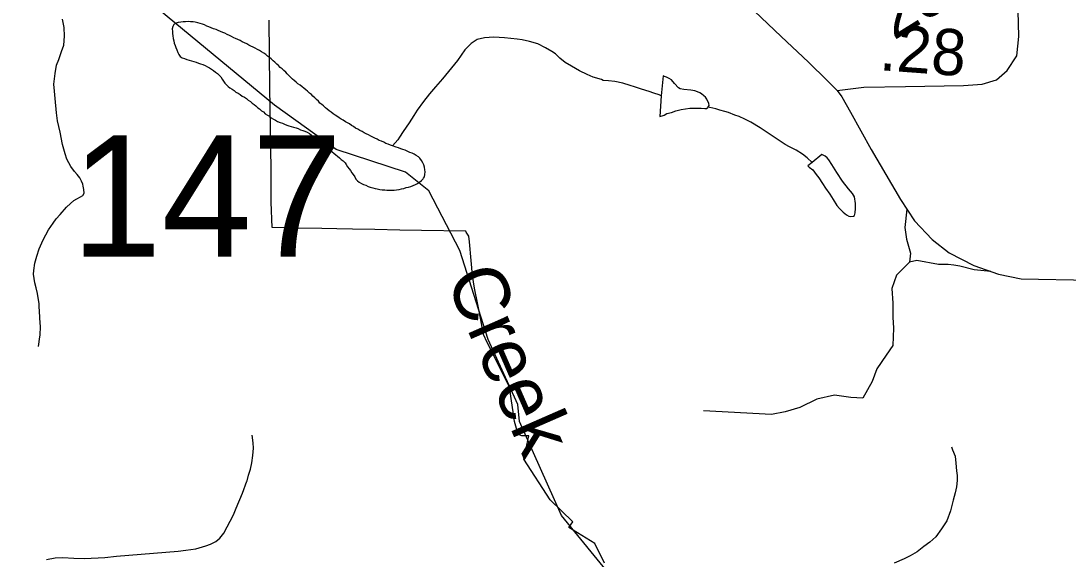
# Model space of a CAD drawing. Extents: x 2001466 to 31450019, y -30647475 to 847247.
# Drawn here: x 2153501 to 2159166, y 761240 to 764149 of the extents above; entities that cross this region are included whole.
import ezdxf

# ---------------------------------------------------------------- set-up
doc = ezdxf.new("R2010")
doc.units = 0
for name, color, linetype in [('Exist Boundary Political City Limit New', 7, 'Continuous'), ('Exist Hydrographic Creek Single Shore', 7, 'Continuous'), ('Exist Hydrographic Creek Single Shore Label', 7, 'Continuous'), ('Exist Hydrographic Misc Water Feature', 7, 'Continuous'), ('Exist Road Non-System Type 51', 7, 'Continuous'), ('Exist Road Secondary Mileage Hundredths English Label', 7, 'Continuous'), ('Exist Road Secondary Structure Standard Bridge Number Label', 7, 'Continuous'), ('Exist Road Secondary Type 51 Attributed', 7, 'Continuous'), ('Exist Road Secondary Type 51 Number Label', 7, 'Continuous'), ('Map Preparation Boundary City Limit Buffer Line', 7, 'Continuous')]:
    doc.layers.add(name, color=color, linetype=linetype)

msp = doc.modelspace()

# ---------------------------------------------------------------- linework, layer by layer
at = {"layer": 'Exist Boundary Political City Limit New'}
msp.add_lwpolyline([(2156657.8, 761217.6), (2156606, 761323.4), (2156464.8, 761410.4), (2156487, 761441.2), (2156363.2, 761559.5), (2156220.8, 761779.9), (2156249.2, 761906.5), (2156210, 761905.6), (2156195.5, 761910.8), (2156186.2, 761932.5), (2156172, 761983.3), (2156165, 762022.5), (2156152.5, 762108.3), (2156144, 762171.1), (2156023.2, 762411.2), (2156003.8, 762453.4), (2155988.5, 762533), (2155973, 762616.8), (2155955, 762703.8), (2155944, 762772.4), (2155936.2, 762853.9), (2155926.8, 762954.9), (2155923.5, 762985.4), (2155909.8, 763007.9), (2155907, 763013.1), (2155668.2, 763015.9), (2155551.2, 763017.9), (2155415.5, 763020.9), (2155295.5, 763023.9), (2155209.2, 763025.1), (2155129, 763026.2), (2155000, 763028.9), (2154859.2, 763031.7), (2154855.2, 763168.5), (2154854.5, 763348.4), (2154850.8, 763568.4), (2154847.5, 763788.2), (2154843, 764152.2)], dxfattribs=at)
at = {"layer": 'Exist Hydrographic Creek Single Shore'}
msp.add_lwpolyline([(2156794.2, 761022.6), (2156425.3, 761476.3), (2156197.3, 761982.9), (2156189.3, 762075), (2156028.3, 762426), (2155876.2, 762908.1), (2155707.2, 763229.7), (2155582.3, 763330.7), (2155206.3, 763453.2), (2154872.2, 763693.1), (2154043.2, 764379.3), (2153717.2, 764612.4), (2153524.2, 764783.6), (2153339.3, 765049.9), (2153113.3, 765274.3), (2153096.3, 765333.7)], dxfattribs=at)
at = {"layer": 'Exist Hydrographic Misc Water Feature'}
for points in [[(2153596.4, 762388.9), (2153597.8, 762400.9), (2153602.2, 762429), (2153605.6, 762452.9), (2153607.5, 762494.7), (2153603.2, 762542.9), (2153600.9, 762583), (2153599.1, 762599.1), (2153598.9, 762618.9), (2153590.5, 762675), (2153582.5, 762706.6), (2153576.3, 762732.7), (2153569.8, 762780.8), (2153570.2, 762800.6), (2153575.7, 762838.7), (2153587.4, 762876.6), (2153599.3, 762916.7), (2153620.8, 762964.9), (2153650.8, 763018.8), (2153674.5, 763055), (2153692.2, 763079.5), (2153712.3, 763103.2), (2153747.9, 763141.6), (2153769.7, 763161.9), (2153787.7, 763177.8), (2153803.7, 763188), (2153823.2, 763198), (2153835.7, 763205.9), (2153843.7, 763218), (2153841.5, 763237.8), (2153837.1, 763255.9), (2153835.5, 763265.9), (2153828.7, 763281.9), (2153825, 763289.8), (2153819.1, 763300), (2153805, 763318), (2153791, 763335.5), (2153770.7, 763361.7), (2153748.4, 763401.6), (2153740.4, 763429.6), (2153726, 763481.2), (2153713.5, 763547.2), (2153699.1, 763609), (2153693, 763653), (2153686.8, 763728.9), (2153682.5, 763768.9), (2153678.2, 763806.9), (2153685.8, 763865), (2153693.4, 763908.9), (2153705.7, 763941.1), (2153721.3, 763983.4), (2153732.8, 764017.3), (2153736.9, 764067.4), (2153734.4, 764113.2), (2153726.2, 764159.1)], [(2154417.9, 764144.9), (2154406, 764145.1), (2154391.8, 764144.8), (2154377.9, 764144.9), (2154366, 764142.6), (2154352, 764140.6), (2154340.3, 764136.7), (2154328.2, 764130.5), (2154322.1, 764118.4), (2154320, 764106.5), (2154320.2, 764092.3), (2154320.5, 764080.6), (2154322.7, 764068.5), (2154324.6, 764054.4), (2154328.7, 764040.8), (2154330.5, 764028.7), (2154334.8, 764016.7), (2154338.9, 764004.7), (2154344.9, 763992.8), (2154349, 763978.8), (2154355.1, 763966.6), (2154363.1, 763956.9), (2154373.4, 763948.8), (2154385.5, 763945), (2154397.6, 763941.1), (2154411.3, 763937), (2154423.4, 763933.1), (2154435.5, 763929.3), (2154449.2, 763925.2), (2154461.3, 763921.3), (2154473, 763917.5), (2154485.1, 763913.6), (2154497.4, 763907.7), (2154509.5, 763901.4), (2154521.2, 763895.6), (2154531.5, 763887.6), (2154543.6, 763881.7), (2154553.4, 763872.1), (2154563.6, 763864.1), (2154573.7, 763856), (2154581.9, 763845.9), (2154589.7, 763834.1), (2154596, 763824.2), (2154603.8, 763812.1), (2154611.8, 763804.4), (2154622.1, 763794.4), (2154631.9, 763786.4), (2154644, 763780.5), (2154654.1, 763772.5), (2154664.3, 763764.5), (2154676, 763758.6), (2154686.3, 763750.6), (2154698.2, 763742.7), (2154710.3, 763736.8), (2154720.5, 763728.8), (2154730.1, 763720.8), (2154742.5, 763712.9), (2154752.5, 763704.8), (2154762.8, 763697.2), (2154772.4, 763689.3), (2154782.2, 763679.3), (2154792.3, 763673.3), (2154802.5, 763663.2), (2154812.8, 763657.6), (2154822.8, 763647.5), (2154834.7, 763639.7), (2154844.8, 763633.7), (2154855, 763625.7), (2154866.9, 763617.8), (2154879, 763611.9), (2154889.1, 763605.9), (2154903, 763599.8), (2154915.1, 763595.9), (2154926.8, 763590.1), (2154938.9, 763586.2), (2154951, 763582.3), (2154963.1, 763578.1), (2154975.2, 763574.2), (2154989.3, 763570.4), (2155001, 763566.6), (2155013.3, 763560.3), (2155025.4, 763556.5), (2155037.5, 763552.6), (2155049.2, 763546.8), (2155061.3, 763540.9), (2155071.1, 763533), (2155081.4, 763522.9), (2155089.6, 763513.1), (2155099.7, 763505.1), (2155109.5, 763495.1), (2155119.5, 763487.1), (2155129.6, 763481.1), (2155141.7, 763471.2), (2155151.7, 763463.6), (2155161.8, 763457.6), (2155172, 763449.6), (2155183.9, 763441.7), (2155194, 763433.6), (2155204, 763425.6), (2155214.3, 763417.6)], [(2155511.2, 763473.3), (2155499.7, 763477.4), (2155487.4, 763483.3), (2155475.3, 763487.2), (2155463.6, 763493.1), (2155451.3, 763499), (2155439.2, 763502.8), (2155427.5, 763509.1), (2155415.4, 763515), (2155405.4, 763520.9), (2155393.5, 763526.8), (2155381.4, 763532.7), (2155369.1, 763538.6), (2155357.4, 763544.4), (2155347.4, 763550.4), (2155335.1, 763556.3), (2155322.7, 763564.2), (2155311.1, 763570.1), (2155301, 763578.1), (2155288.7, 763584), (2155279.1, 763592), (2155266.8, 763597.9), (2155256.7, 763603.9), (2155244.8, 763611.7), (2155232.7, 763617.6), (2155222.5, 763625.6), (2155210.8, 763633.5), (2155200.7, 763639.5), (2155190.5, 763647.5), (2155178.6, 763655.4), (2155168.5, 763663.4), (2155158.3, 763671.5), (2155148.7, 763679.4), (2155138.4, 763689.1), (2155128.6, 763697.1), (2155118.5, 763705.1), (2155110.3, 763715.2), (2155100.1, 763724.9), (2155090.4, 763732.8), (2155080.2, 763742.9), (2155072.2, 763751), (2155061.9, 763758.7), (2155052.1, 763768.7), (2155042, 763776.7), (2155032, 763784.7), (2155022.1, 763792.7), (2155011.5, 763802.4), (2154999.8, 763808.7), (2154989.9, 763818.2), (2154979.7, 763826.3), (2154970.1, 763834.2), (2154961.4, 763844), (2154951.8, 763852), (2154941.6, 763862.1), (2154933.4, 763872.2), (2154923.7, 763880.2), (2154913.5, 763889.9), (2154903.2, 763897.9), (2154895, 763907.6), (2154885, 763915.6), (2154875.1, 763925.6), (2154865.5, 763933.6), (2154855.2, 763943.7), (2154845, 763951.3), (2154834.9, 763959.3), (2154825.1, 763967.3), (2154815, 763975.3), (2154802.7, 763981.2), (2154791, 763989.1), (2154781, 763995.1), (2154768.7, 764001), (2154757, 764006.8), (2154744.9, 764013.1), (2154734.7, 764018.7), (2154723, 764024.9), (2154710.9, 764030.8), (2154698.6, 764036.7), (2154686.5, 764042.6), (2154674.6, 764048.5), (2154662.5, 764054.4), (2154652.4, 764058.3), (2154640.7, 764064.2), (2154628.4, 764070), (2154616.3, 764076.4), (2154604.7, 764082.2), (2154592.6, 764086), (2154580.3, 764091.9), (2154568.2, 764097.8), (2154556.5, 764102), (2154542.3, 764105.8), (2154530, 764111.7), (2154518.3, 764117.6), (2154506.2, 764121.4), (2154494.5, 764127.7), (2154482.4, 764131.5), (2154469.7, 764135.4), (2154458, 764139.3), (2154444.1, 764141.4), (2154432, 764143.2), (2154417.9, 764144.9)], [(2156965.4, 763743.3), (2156953.7, 763749.6), (2156925.6, 763759.1), (2156899.2, 763767.2), (2156857.4, 763780.8), (2156821.1, 763792.8), (2156797.3, 763800.5), (2156757.1, 763812.2), (2156713.4, 763822), (2156679.2, 763826), (2156651.5, 763827.8), (2156641.4, 763831.7), (2156596.9, 763845.4), (2156564.7, 763859.1), (2156523.1, 763878.8), (2156478.8, 763904.6), (2156444.8, 763924.4), (2156416.5, 763948.5), (2156392.5, 763970.4), (2156372.2, 763984), (2156338.2, 764003.8), (2156298, 764025.7), (2156252.5, 764037.4), (2156212.1, 764047.2), (2156185.8, 764051.1), (2156116.3, 764056.8), (2156059.9, 764060.4), (2156008, 764058.1), (2155968.3, 764048), (2155936.3, 764027.6), (2155902.6, 763993.4), (2155862.7, 763935.3), (2155813.2, 763875), (2155781.2, 763836.8), (2155743.7, 763792.7), (2155711.9, 763754.5), (2155678.5, 763714.1), (2155644.5, 763666.1), (2155626.6, 763637.9), (2155600.8, 763598.1), (2155569, 763551.8), (2155549.5, 763521.4), (2155539.1, 763505.5), (2155511.2, 763473.3)], [(2157219.7, 763685.1), (2157223.6, 763690.9), (2157221.7, 763703), (2157211.3, 763726.8), (2157203.7, 763736.9), (2157195.5, 763744.7), (2157183.2, 763754.6), (2157173.5, 763760.6), (2157161.5, 763766.5), (2157147.1, 763770.6), (2157125.4, 763774.4), (2157087.2, 763778.1), (2157067.5, 763781.9), (2157057.5, 763787.8), (2157037.4, 763810), (2157021, 763829.9), (2157008.7, 763837.8), (2156993.1, 763845.5), (2156983.1, 763849.4), (2156974.9, 763851.5), (2156965.4, 763743.3)], [(2156965.4, 763743.3), (2156958.2, 763631.6), (2156969.9, 763635.6), (2156980, 763639.7), (2156995.8, 763647.9), (2157019.8, 763654), (2157044.2, 763662.1), (2157072.3, 763670), (2157095.8, 763674.1), (2157120, 763676.6), (2157158, 763676.6), (2157180.1, 763676.8), (2157200.2, 763675), (2157209.8, 763674.8), (2157217.6, 763680.9), (2157219.7, 763685.1)], [(2157781.5, 763384.2), (2157755.3, 763408.1), (2157728.8, 763427.9), (2157695, 763449.7), (2157658.9, 763467.7), (2157634.9, 763481.4), (2157581, 763516.8), (2157548.4, 763538.8), (2157500.6, 763570.3), (2157450.2, 763602.3), (2157418, 763618.1), (2157385.8, 763631.9), (2157362.2, 763639.9), (2157328, 763653.6), (2157308.1, 763659.5), (2157282, 763667.1), (2157260.1, 763673.2), (2157227.9, 763681), (2157219.7, 763685.1)], [(2155678.5, 763298.3), (2155684.5, 763306.3), (2155686.5, 763318.6), (2155687.9, 763332.5), (2155686.1, 763344.6), (2155684.3, 763358.3), (2155679.7, 763370.3), (2155675.8, 763382.2), (2155668.1, 763394.4), (2155659.4, 763406.2), (2155651.9, 763414.3), (2155639.6, 763422.2), (2155627.9, 763428), (2155617.8, 763434), (2155605.7, 763437.9), (2155593.8, 763443.7), (2155579.7, 763450), (2155567.6, 763453.8), (2155555.5, 763457.7), (2155543.6, 763463.5), (2155531.5, 763467.3), (2155511.2, 763473.3)], [(2155214.3, 763417.6), (2155223.9, 763409.6), (2155233.8, 763400), (2155244, 763392), (2155254.3, 763381.9), (2155260.2, 763372.1), (2155268, 763360), (2155276.2, 763350.2), (2155284.2, 763340.1), (2155290.8, 763328.1), (2155298.3, 763318.1), (2155306.5, 763306.2), (2155312.3, 763294.4), (2155320.9, 763284.2), (2155331, 763278.2), (2155342.6, 763270.3), (2155354.9, 763264.4), (2155367, 763260.6), (2155378.7, 763254.8), (2155390.8, 763250.9), (2155404.8, 763246.8), (2155416.9, 763242.9), (2155428.8, 763241.1), (2155442.9, 763237), (2155455, 763235.1), (2155469, 763235), (2155481, 763233.2), (2155495.2, 763233.5), (2155506.9, 763233.3), (2155521, 763233.3), (2155532.9, 763235.5), (2155546.9, 763237.5), (2155559, 763241.7), (2155572.9, 763243.7), (2155584.6, 763248), (2155598.5, 763249.9), (2155610.8, 763254.2), (2155622.7, 763260), (2155635, 763264.3), (2155646.5, 763270.2), (2155656.4, 763278.1), (2155668.5, 763286.4), (2155676.5, 763294.5), (2155678.5, 763298.3)], [(2157781.5, 763384.2), (2157757.5, 763365.9), (2157765.7, 763358.3), (2157785.4, 763344.3), (2157803.7, 763318.4), (2157817.6, 763300.5), (2157837.7, 763270.7), (2157853.9, 763244.7), (2157876.3, 763212.9), (2157894.5, 763183), (2157914.4, 763151.2), (2157928.8, 763135.2), (2157948.9, 763115.2), (2157966.9, 763101.4), (2157979.2, 763093.5), (2157990.7, 763091.4), (2158005, 763093.6), (2158010.8, 763097.6), (2158014.5, 763111.7), (2158016.7, 763135.7), (2158016.5, 763161.7), (2158010.2, 763197.5), (2158000.3, 763215.6), (2157977.8, 763241.4), (2157945.8, 763283.2), (2157915.6, 763329.1), (2157887.5, 763372.7), (2157871.1, 763398.7), (2157863.3, 763408.8), (2157851.5, 763418.7), (2157833.2, 763426.3), (2157781.5, 763384.2)], [(2158535.7, 761846.7), (2158539.8, 761830.7), (2158554.2, 761796.9), (2158558.5, 761758.9), (2158562.6, 761716.9), (2158566.7, 761691.1), (2158566.7, 761665.2), (2158563, 761631.2), (2158555.2, 761597.1), (2158543.5, 761559.1), (2158530, 761500.7), (2158509.9, 761447), (2158482, 761402.5), (2158450.4, 761360.6), (2158418.6, 761330.6), (2158386.4, 761308.3), (2158349.1, 761279.9), (2158311, 761257.6), (2158279.4, 761241.7), (2158225.7, 761217.4)]]:
    msp.add_lwpolyline(points, dxfattribs=at)
at = {"layer": 'Exist Road Non-System Type 51'}
for points in [[(2158293.5, 763130.7), (2158282.8, 763031.5), (2158291.3, 762969.5), (2158313.8, 762893.5), (2158308.1, 762845.6)], [(2158308.1, 762845.6), (2158237.8, 762775.2), (2158212.4, 762701.9), (2158218.1, 762623.1), (2158218.1, 762547), (2158220.9, 762487.9), (2158218.1, 762394.9), (2158181.5, 762341.4), (2158130.8, 762268.2), (2158105.5, 762200.6), (2158054.8, 762110.4), (2157991.4, 762113.3), (2157901.9, 762125.4), (2157807.1, 762104.8), (2157714.2, 762059.7), (2157636.2, 762035.8), (2157561.8, 762022.2), (2157193, 762041.9)], [(2158748.8, 762793.6), (2158657.8, 762802.7), (2158581.2, 762823.1), (2158547.4, 762828.7), (2158516.4, 762831.5), (2158465.8, 762831.5), (2158347.5, 762854), (2158308.1, 762845.6)], [(2153639.3, 761237.6), (2153685.3, 761246.1), (2153727.3, 761248.6), (2153787.2, 761245.2), (2153845.4, 761243.8), (2153955.3, 761249), (2154017.2, 761255.7), (2154351.1, 761283.2), (2154393, 761287.6), (2154447, 761296.1), (2154500.9, 761310.8), (2154526.7, 761321), (2154554.6, 761335.3), (2154576.3, 761353.4), (2154598.1, 761379.8), (2154651.1, 761478.3), (2154664.6, 761514.4), (2154699.7, 761596.9), (2154723.2, 761661), (2154725.1, 761663.1), (2154732.9, 761693.2), (2154742.6, 761725.2), (2154750.1, 761759.4), (2154755.7, 761799.5), (2154759.3, 761839.4), (2154756.9, 761867.5), (2154752.5, 761909.3)]]:
    msp.add_lwpolyline(points, dxfattribs=at)
at = {"layer": 'Exist Road Secondary Type 51 Attributed'}
for points in [[(2157082.7, 764578.5), (2157204.7, 764462.3), (2157398.2, 764272.7), (2157613.3, 764064.4), (2157760.8, 763926.1), (2157862.3, 763826.7), (2157917.2, 763772.2)], [(2157917.2, 763772.2), (2158060.1, 763790), (2158286.1, 763795.2), (2158600.5, 763800.5), (2158701, 763807.8), (2158778.4, 763830.8), (2158836, 763880.1), (2158888.8, 763959.6), (2158899.3, 764065.4), (2158896.1, 764203.6), (2158910.3, 764381.6)], [(2157917.2, 763772.2), (2157942.3, 763738.7), (2157989.4, 763656), (2158099.8, 763453.9), (2158258.9, 763183.7), (2158334.2, 763068.5), (2158430.5, 762968), (2158522.6, 762894.7), (2158655.5, 762827.7), (2158789.4, 762779.5), (2158912.9, 762754.4), (2159289.6, 762748.1), (2160263.7, 762706.2), (2160768.1, 762685.3), (2161673.2, 762645.5), (2162311.5, 762624.6), (2163007.4, 762607.8), (2163373.6, 762601.5), (2163808.9, 762595.2), (2163901.5, 762585.8)]]:
    msp.add_lwpolyline(points, dxfattribs=at)
at = {"layer": 'Map Preparation Boundary City Limit Buffer Line'}
msp.add_lwpolyline([(2156657.8, 761217.6), (2156606, 761323.4), (2156464.8, 761410.4), (2156487, 761441.2), (2156363.2, 761559.5), (2156220.8, 761779.9), (2156249.2, 761906.5), (2156210, 761905.6), (2156195.5, 761910.8), (2156186.2, 761932.5), (2156172, 761983.3), (2156165, 762022.5), (2156152.5, 762108.3), (2156144, 762171.1), (2156023.2, 762411.2), (2156003.8, 762453.4), (2155988.5, 762533), (2155973, 762616.8), (2155955, 762703.8), (2155944, 762772.4), (2155936.2, 762853.9), (2155926.8, 762954.9), (2155923.5, 762985.4), (2155909.8, 763007.9), (2155907, 763013.1), (2155668.2, 763015.9), (2155551.2, 763017.9), (2155415.5, 763020.9), (2155295.5, 763023.9), (2155209.2, 763025.1), (2155129, 763026.2), (2155000, 763028.9), (2154859.2, 763031.7), (2154855.2, 763168.5), (2154854.5, 763348.4), (2154850.8, 763568.4), (2154847.5, 763788.2), (2154843, 764152.2)], dxfattribs=at)

# ---------------------------------------------------------------- texts
at = {"layer": 'Exist Hydrographic Creek Single Shore Label'}
msp.add_text('Creek', height=300, rotation=293.6129, dxfattribs=at).set_placement((2155795.6, 762752.6))
at = {"layer": 'Exist Road Secondary Mileage Hundredths English Label'}
msp.add_text('.28', height=250, rotation=355.8131, dxfattribs=at).set_placement((2158141.3, 763883.2))
at = {"layer": 'Exist Road Secondary Structure Standard Bridge Number Label'}
msp.add_text('147', height=656.17, dxfattribs=at).set_placement((2153773.9, 762874.1))
at = {"layer": 'Exist Road Secondary Type 51 Number Label'}
msp.add_text('2971', height=250, rotation=31.918, dxfattribs=at).set_placement((2158223.8, 764042))

doc.saveas('drawing.dxf')
